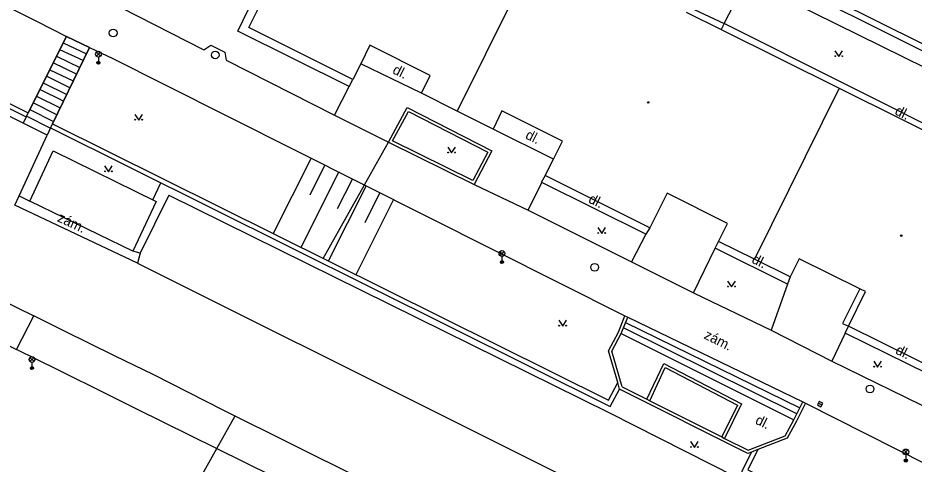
# Model space of a CAD drawing. Extents: x -602419 to -601554, y -1162937 to -1162362.
# Drawn here: x -602127.5 to -602069.2, y -1162458.3 to -1162429.2 of the extents above; entities that cross this region are included whole.
import ezdxf

# ---------------------------------------------------------------- set-up
doc = ezdxf.new("R2010")
doc.units = 0
doc.layers.add('Podklad', color=7, linetype='Continuous')

msp = doc.modelspace()

# ---------------------------------------------------------------- linework, layer by layer
at = {"layer": 'Podklad'}
for p, q in [((-602122.3725, -1162431.74), (-602122.1075, -1162431.475)), ((-602122.3725, -1162431.475), (-602122.1075, -1162431.74)), ((-602122.24, -1162431.795), (-602122.24, -1162432.17)), ((-602096.1225, -1162444.71), (-602095.8575, -1162444.445)), ((-602096.1225, -1162444.445), (-602095.8575, -1162444.71)), ((-602095.99, -1162444.765), (-602095.99, -1162445.14)), ((-602126.6925, -1162451.61), (-602126.4275, -1162451.345)), ((-602126.6925, -1162451.345), (-602126.4275, -1162451.61)), ((-602126.56, -1162451.665), (-602126.56, -1162452.04)), ((-602075.4101, -1162454.3208), (-602075.1899, -1162454.4392)), ((-602069.8524, -1162457.63), (-602069.5874, -1162457.365)), ((-602069.8524, -1162457.365), (-602069.5874, -1162457.63)), ((-602069.7199, -1162457.685), (-602069.7199, -1162458.06))]:
    msp.add_line(p, q, dxfattribs=at)
for points in [[(-602110.75, -1162410.35), (-602085.9699, -1162422.74), (-602065.88, -1162432.75)], [(-602110.59, -1162410.03), (-602105.99, -1162412.28), (-602092.51, -1162419.02), (-602085.79, -1162422.38), (-602065.86, -1162432.31), (-602062.11, -1162430.76), (-602051.04, -1162436.18), (-602050.17, -1162439.85), (-602040.49, -1162444.95), (-602033.93, -1162447.87), (-602033.51, -1162450.86), (-602033.9099, -1162450.92)], [(-602202.73, -1162410.9099), (-602189.44, -1162417.46), (-602167.49, -1162428.34), (-602160.15, -1162431.98), (-602154.43, -1162434.82), (-602132.77, -1162445.48), (-602129.7, -1162447.06), (-602126.44, -1162448.64)], [(-602159.7199, -1162412.76), (-602157.26, -1162413.99), (-602151.36, -1162416.93), (-602126.27, -1162429.4699), (-602124.32, -1162430.46)], [(-602162.51, -1162415.67), (-602163.34, -1162417.29), (-602126.8, -1162435.42)], [(-602162.92, -1162415.82), (-602163.74, -1162417.42), (-602126.94, -1162435.69)], [(-602127.13, -1162436.09), (-602152.5, -1162423.55), (-602158.33, -1162420.67), (-602164.1, -1162417.86)], [(-602119.2, -1162423.65), (-602121.46, -1162428.23), (-602120.73, -1162428.59), (-602115.38, -1162431.32), (-602114.92, -1162431.02), (-602114.02, -1162431.48), (-602113.94, -1162432), (-602106.89, -1162435.57)], [(-602093.39, -1162424.2199), (-602098.9, -1162435.31)], [(-602081.53, -1162429.62), (-602080.07, -1162426.74), (-602062.63, -1162435.36), (-602064.21, -1162438.3)], [(-602113.18, -1162430.12), (-602112.1, -1162427.9099)], [(-602112.46, -1162429.88), (-602111.34, -1162427.64)], [(-602084, -1162428.88), (-602081.74, -1162430)], [(-602083.82, -1162428.56), (-602081.53, -1162429.62)], [(-602081.53, -1162429.62), (-602081.74, -1162430)], [(-602065.79, -1162437.52), (-602081.53, -1162429.62)], [(-602105.93, -1162433.71), (-602113.18, -1162430.12)], [(-602105.7, -1162433.26), (-602112.46, -1162429.88)], [(-602081.74, -1162430), (-602074.05, -1162433.83)], [(-602126.8, -1162435.42), (-602124.32, -1162430.46)], [(-602124.32, -1162430.46), (-602126.8, -1162435.42)], [(-602122.82, -1162431.17), (-602124.32, -1162430.46)], [(-602124.32, -1162430.46), (-602122.82, -1162431.17)], [(-602125.23, -1162436.14), (-602122.82, -1162431.17)], [(-602122.82, -1162431.17), (-602125.23, -1162436.14)], [(-602123.23, -1162432.02), (-602124.75, -1162431.32)], [(-602124.53, -1162430.88), (-602123.02, -1162431.58)], [(-602122.82, -1162431.17), (-602121.31, -1162431.89), (-602117.98, -1162433.56), (-602087.99, -1162448.63)], [(-602104.58, -1162431.03), (-602105.18, -1162432.24)], [(-602100.65, -1162432.99), (-602104.58, -1162431.03)], [(-602074.33, -1162431.385), (-602074.08, -1162431.76), (-602073.83, -1162431.385)], [(-602124.96, -1162431.74), (-602123.45, -1162432.4699)], [(-602123.6599, -1162432.9099), (-602125.18, -1162432.18)], [(-602105.18, -1162432.24), (-602105.7, -1162433.26)], [(-602101.23, -1162434.15), (-602105.18, -1162432.24)], [(-602124.09, -1162433.79), (-602125.62, -1162433.05)], [(-602125.4, -1162432.62), (-602123.88, -1162433.35)], [(-602101.23, -1162434.15), (-602100.65, -1162432.99)], [(-602125.83, -1162433.48), (-602124.3, -1162434.23)], [(-602106.89, -1162435.57), (-602105.93, -1162433.71)], [(-602105.93, -1162433.71), (-602105.7, -1162433.26)], [(-602124.52, -1162434.67), (-602126.05, -1162433.9099)], [(-602098.9, -1162435.31), (-602101.23, -1162434.15)], [(-602074.05, -1162433.83), (-602079.57, -1162444.95)], [(-602074.05, -1162433.83), (-602065.95, -1162437.85)], [(-602124.94, -1162435.55), (-602126.49, -1162434.78)], [(-602126.27, -1162434.35), (-602124.73, -1162435.11)], [(-602126.94, -1162435.69), (-602126.8, -1162435.42)], [(-602126.8, -1162435.42), (-602126.94, -1162435.69)], [(-602126.7, -1162435.2199), (-602125.1599, -1162435.99)], [(-602103.38, -1162437.34), (-602102.1599, -1162435.08), (-602096.64, -1162437.89), (-602097.8, -1162440.09)], [(-602103.1, -1162437.25), (-602102.08, -1162435.34), (-602096.9099, -1162437.98), (-602097.88, -1162439.83), (-602103.1, -1162437.25)], [(-602096.57, -1162436.48), (-602098.9, -1162435.31)], [(-602095.99, -1162435.3), (-602096.57, -1162436.48)], [(-602092.05, -1162437.26), (-602095.99, -1162435.3)], [(-602126.94, -1162435.69), (-602127.13, -1162436.09)], [(-602125.37, -1162436.43), (-602126.92, -1162435.65)], [(-602119.87, -1162435.525), (-602119.62, -1162435.9), (-602119.37, -1162435.525)], [(-602106.89, -1162435.57), (-602103.38, -1162437.34)], [(-602125.58, -1162436.89), (-602127.13, -1162436.09)], [(-602125.36, -1162436.4099), (-602125.58, -1162436.89)], [(-602125.36, -1162436.4099), (-602125.23, -1162436.14)], [(-602125.23, -1162436.14), (-602125.36, -1162436.4099)], [(-602125.36, -1162436.4099), (-602088.95, -1162454.53), (-602088.34, -1162453.4)], [(-602125.23, -1162436.14), (-602089.07, -1162454.13), (-602088.46, -1162452.98)], [(-602092.64, -1162438.44), (-602096.57, -1162436.48)], [(-602127.39, -1162440.82), (-602125.58, -1162436.89)], [(-602107.6125, -1162444.9049), (-602104.929, -1162440.1181), (-602103.38, -1162437.34)], [(-602103.38, -1162437.34), (-602097.8, -1162440.09)], [(-602099.52, -1162437.665), (-602099.27, -1162438.04), (-602099.02, -1162437.665)], [(-602092.64, -1162438.44), (-602092.05, -1162437.26)], [(-602126.71, -1162441.18), (-602125.19, -1162437.9)], [(-602125.19, -1162437.9), (-602118.48, -1162441.2), (-602120, -1162444.43)], [(-602108.4, -1162438.37), (-602110.87, -1162443.29)], [(-602121.84, -1162438.885), (-602121.59, -1162439.26), (-602121.34, -1162438.885)], [(-602107.51, -1162438.82), (-602108.49, -1162440.79)], [(-602093.17, -1162439.5), (-602092.64, -1162438.44)], [(-602106.61, -1162439.27), (-602109.08, -1162444.18)], [(-602093.17, -1162439.5), (-602093.43, -1162439.95)], [(-602086.37, -1162442.9), (-602093.17, -1162439.5)], [(-602118.6964, -1162441.0936), (-602118.1749, -1162439.9857)], [(-602105.7199, -1162439.7199), (-602106.7, -1162441.68)], [(-602097.8, -1162440.09), (-602094.29, -1162441.76)], [(-602094.29, -1162441.76), (-602093.4, -1162439.96)], [(-602093.4, -1162439.96), (-602093.43, -1162439.95)], [(-602086.63, -1162443.33), (-602093.4, -1162439.96)], [(-602104.82, -1162440.17), (-602107.29, -1162445.07)], [(-602103.93, -1162440.62), (-602104.92, -1162442.58)], [(-602085.25, -1162440.6599), (-602086.37, -1162442.9)], [(-602081.32, -1162442.63), (-602085.25, -1162440.6599)], [(-602119.53, -1162444.57), (-602119.69, -1162445.21), (-602127.68, -1162441.44), (-602127.39, -1162440.82)], [(-602127.39, -1162440.82), (-602126.71, -1162441.18)], [(-602120, -1162444.43), (-602126.71, -1162441.18)], [(-602117.65, -1162440.79), (-602119.53, -1162444.57)], [(-602117.65, -1162440.79), (-602089.04, -1162454.93)], [(-602103.04, -1162441.07), (-602105.5, -1162445.96)], [(-602094.29, -1162441.76), (-602087.56, -1162445.12)], [(-602089.75, -1162442.895), (-602089.5, -1162443.27), (-602089.25, -1162442.895)], [(-602086.37, -1162442.9), (-602086.63, -1162443.33)], [(-602081.9, -1162443.79), (-602081.32, -1162442.63)], [(-602086.63, -1162443.33), (-602087.56, -1162445.12)], [(-602083.54, -1162447.13), (-602082.12, -1162444.24)], [(-602082.12, -1162444.24), (-602081.9, -1162443.79)], [(-602077.4099, -1162446.58), (-602082.12, -1162444.24)], [(-602079.57, -1162444.95), (-602081.9, -1162443.79)], [(-602119.53, -1162444.57), (-602120, -1162444.43)], [(-602119.69, -1162445.21), (-602056.89, -1162476.59)], [(-602087.56, -1162445.12), (-602083.54, -1162447.13)], [(-602077.24, -1162446.1), (-602079.57, -1162444.95)], [(-602076.6599, -1162444.93), (-602077.24, -1162446.1)], [(-602072.7199, -1162446.88), (-602076.6599, -1162444.93)], [(-602081.31, -1162446.375), (-602081.06, -1162446.75), (-602080.81, -1162446.375)], [(-602077.24, -1162446.1), (-602077.4099, -1162446.58)], [(-602083.54, -1162447.13), (-602078.4699, -1162449.58)], [(-602077.4099, -1162446.58), (-602078.4699, -1162449.58)], [(-602072.7199, -1162446.88), (-602073.83, -1162449.1299), (-602073.46, -1162449.31)], [(-602073.46, -1162449.31), (-602072.35, -1162447.06)], [(-602072.35, -1162447.06), (-602072.7199, -1162446.88)], [(-602130.7, -1162449.29), (-602129.69, -1162449.7699), (-602127.56, -1162450.83), (-602126.44, -1162448.64)], [(-602124.44, -1162449.64), (-602126.44, -1162448.64)], [(-602088.46, -1162452.98), (-602089.06, -1162450.92), (-602088.4099, -1162449.69), (-602087.99, -1162448.63)], [(-602088.23, -1162449.78), (-602087.81, -1162448.7199)], [(-602087.99, -1162448.63), (-602087.81, -1162448.7199)], [(-602087.81, -1162448.7199), (-602076.42, -1162454.23)], [(-602092.29, -1162448.925), (-602092.04, -1162449.3), (-602091.79, -1162448.925)], [(-602076.81, -1162455.02), (-602088.09, -1162449.42)], [(-602087.95, -1162449.07), (-602076.61, -1162454.62)], [(-602073.67, -1162449.76), (-602073.46, -1162449.31)], [(-602067.01, -1162452.49), (-602073.46, -1162449.31)], [(-602121.19, -1162451.25), (-602124.44, -1162449.64)], [(-602088.84, -1162450.94), (-602088.23, -1162449.78)], [(-602088.23, -1162449.78), (-602077.01, -1162455.4099)], [(-602078.4699, -1162449.58), (-602074.54, -1162451.58)], [(-602073.67, -1162449.76), (-602074.54, -1162451.58)], [(-602066.89, -1162453.11), (-602073.67, -1162449.76)], [(-602124.83, -1162452.18), (-602127.56, -1162450.83)], [(-602088.17, -1162453.26), (-602088.84, -1162450.94)], [(-602067.6599, -1162477.83), (-602078.96, -1162472.25), (-602083.03, -1162470.23), (-602092.86, -1162465.34), (-602100.43, -1162461.58), (-602105.24, -1162459.2), (-602114.08, -1162454.79), (-602118.63, -1162452.48), (-602121.19, -1162451.25)], [(-602086.56, -1162454.07), (-602085.4699, -1162451.74), (-602080.4099, -1162454.36), (-602081.51, -1162456.61)], [(-602074.54, -1162451.58), (-602067.79, -1162454.88)], [(-602071.81, -1162451.5949), (-602071.56, -1162451.9699), (-602071.31, -1162451.5949)], [(-602121.69, -1162453.74), (-602124.83, -1162452.18)], [(-602086.38, -1162454.1599), (-602085.38, -1162452.01), (-602080.68, -1162454.45), (-602081.69, -1162456.52)], [(-602088.34, -1162453.4), (-602088.46, -1162452.98)], [(-602079.76, -1162457.5), (-602080, -1162457.59), (-602088.34, -1162453.4)], [(-602088.17, -1162453.26), (-602086.56, -1162454.07)], [(-602110.36, -1162468.9), (-602110.29, -1162468.74), (-602109.38, -1162469.19), (-602105.64, -1162461.67), (-602119.79, -1162454.68), (-602121.69, -1162453.74)], [(-602086.56, -1162454.07), (-602086.38, -1162454.1599)], [(-602086.38, -1162454.1599), (-602081.69, -1162456.52)], [(-602076.24, -1162454.32), (-602076.84, -1162455.5), (-602077.43, -1162456.6), (-602079.34, -1162457.34)], [(-602077.01, -1162455.4099), (-602076.42, -1162454.23)], [(-602076.42, -1162454.23), (-602076.24, -1162454.32)], [(-602076.24, -1162454.32), (-602064.46, -1162460.28), (-602054.34, -1162465.34), (-602051.08, -1162466.92)], [(-602118.7199, -1162464.75), (-602114.54, -1162457.2799), (-602114.5371, -1162457.2749), (-602113.3518, -1162455.1533)], [(-602089.04, -1162454.93), (-602080.77, -1162459.12), (-602054.62, -1162472.2199), (-602056.89, -1162476.59), (-602056.46, -1162476.78)], [(-602077.57, -1162456.44), (-602077.01, -1162455.4099)], [(-602079.98, -1162457.38), (-602077.57, -1162456.44)], [(-602083.7199, -1162456.825), (-602083.4699, -1162457.2), (-602083.2199, -1162456.825)], [(-602081.69, -1162456.52), (-602081.51, -1162456.61)], [(-602081.51, -1162456.61), (-602079.98, -1162457.38)], [(-602079.76, -1162457.5), (-602080.4099, -1162458.78), (-602053.93, -1162472.14)], [(-602079.34, -1162457.34), (-602080, -1162458.65), (-602053.79, -1162471.88)], [(-602079.34, -1162457.34), (-602079.76, -1162457.5)]]:
    msp.add_lwpolyline(points, dxfattribs=at)
msp.add_lwpolyline([(-602075.4693, -1162454.4309), (-602075.2491, -1162454.5493), (-602075.1307, -1162454.3291), (-602075.3509, -1162454.2107)], close=True, dxfattribs=at)
for centre, radius in [((-602121.28, -1162430.23), 0.25), ((-602122.24, -1162431.6075), 0.1875), ((-602114.64, -1162431.6599), 0.25), ((-602074.3051, -1162431.7349), 0.025), ((-602073.8554, -1162431.7349), 0.025), ((-602122.24, -1162432.17), 0.1), ((-602122.24, -1162432.17), 0.0723), ((-602122.24, -1162432.17), 0.0438), ((-602086.48, -1162434.75), 0.045), ((-602086.48, -1162434.75), 0.0199), ((-602119.8451, -1162435.8749), 0.025), ((-602119.3954, -1162435.8749), 0.025), ((-602099.4951, -1162438.0149), 0.025), ((-602099.0454, -1162438.0149), 0.025), ((-602121.8151, -1162439.2349), 0.025), ((-602121.3654, -1162439.2349), 0.025), ((-602089.7251, -1162443.2449), 0.025), ((-602089.2754, -1162443.2449), 0.025), ((-602070.02, -1162443.42), 0.045), ((-602070.02, -1162443.42), 0.0199), ((-602095.99, -1162444.5775), 0.1875), ((-602095.99, -1162445.14), 0.1), ((-602095.99, -1162445.14), 0.0723), ((-602095.99, -1162445.14), 0.0438), ((-602089.96, -1162445.48), 0.25), ((-602081.2851, -1162446.7249), 0.025), ((-602080.8354, -1162446.7249), 0.025), ((-602092.2651, -1162449.2749), 0.025), ((-602091.8154, -1162449.2749), 0.025), ((-602126.56, -1162451.4775), 0.1875), ((-602126.56, -1162452.04), 0.1), ((-602126.56, -1162452.04), 0.0723), ((-602126.56, -1162452.04), 0.0438), ((-602071.7851, -1162451.9448), 0.025), ((-602071.3354, -1162451.9448), 0.025), ((-602072.05, -1162453.4), 0.25), ((-602083.695, -1162457.1749), 0.025), ((-602083.2453, -1162457.1749), 0.025), ((-602069.7199, -1162457.4975), 0.1875), ((-602069.7199, -1162458.06), 0.1), ((-602069.7199, -1162458.06), 0.0723), ((-602069.7199, -1162458.06), 0.0438)]:
    msp.add_circle(centre, radius, dxfattribs=at)

# ---------------------------------------------------------------- texts
for s, rotation, p in [('dl.', 333.49, (-602103.1599, -1162432.83)), ('dl.', 333.49, (-602070.49, -1162435.5)), ('dl.', 333.49, (-602094.52, -1162437.07)), ('dl.', 333.49, (-602090.42, -1162441.24)), (' zám.', 334.74, (-602125.18, -1162442.36)), ('dl.', 333.49, (-602079.8, -1162445.1599)), (' zám.', 333.49, (-602083.12, -1162449.98)), ('dl.', 333.49, (-602070.45, -1162451.07)), ('dl.', 333.49, (-602079.57, -1162455.63))]:
    msp.add_text(s, height=0.65, rotation=rotation, dxfattribs=at).set_placement(p)

doc.saveas('drawing.dxf')
